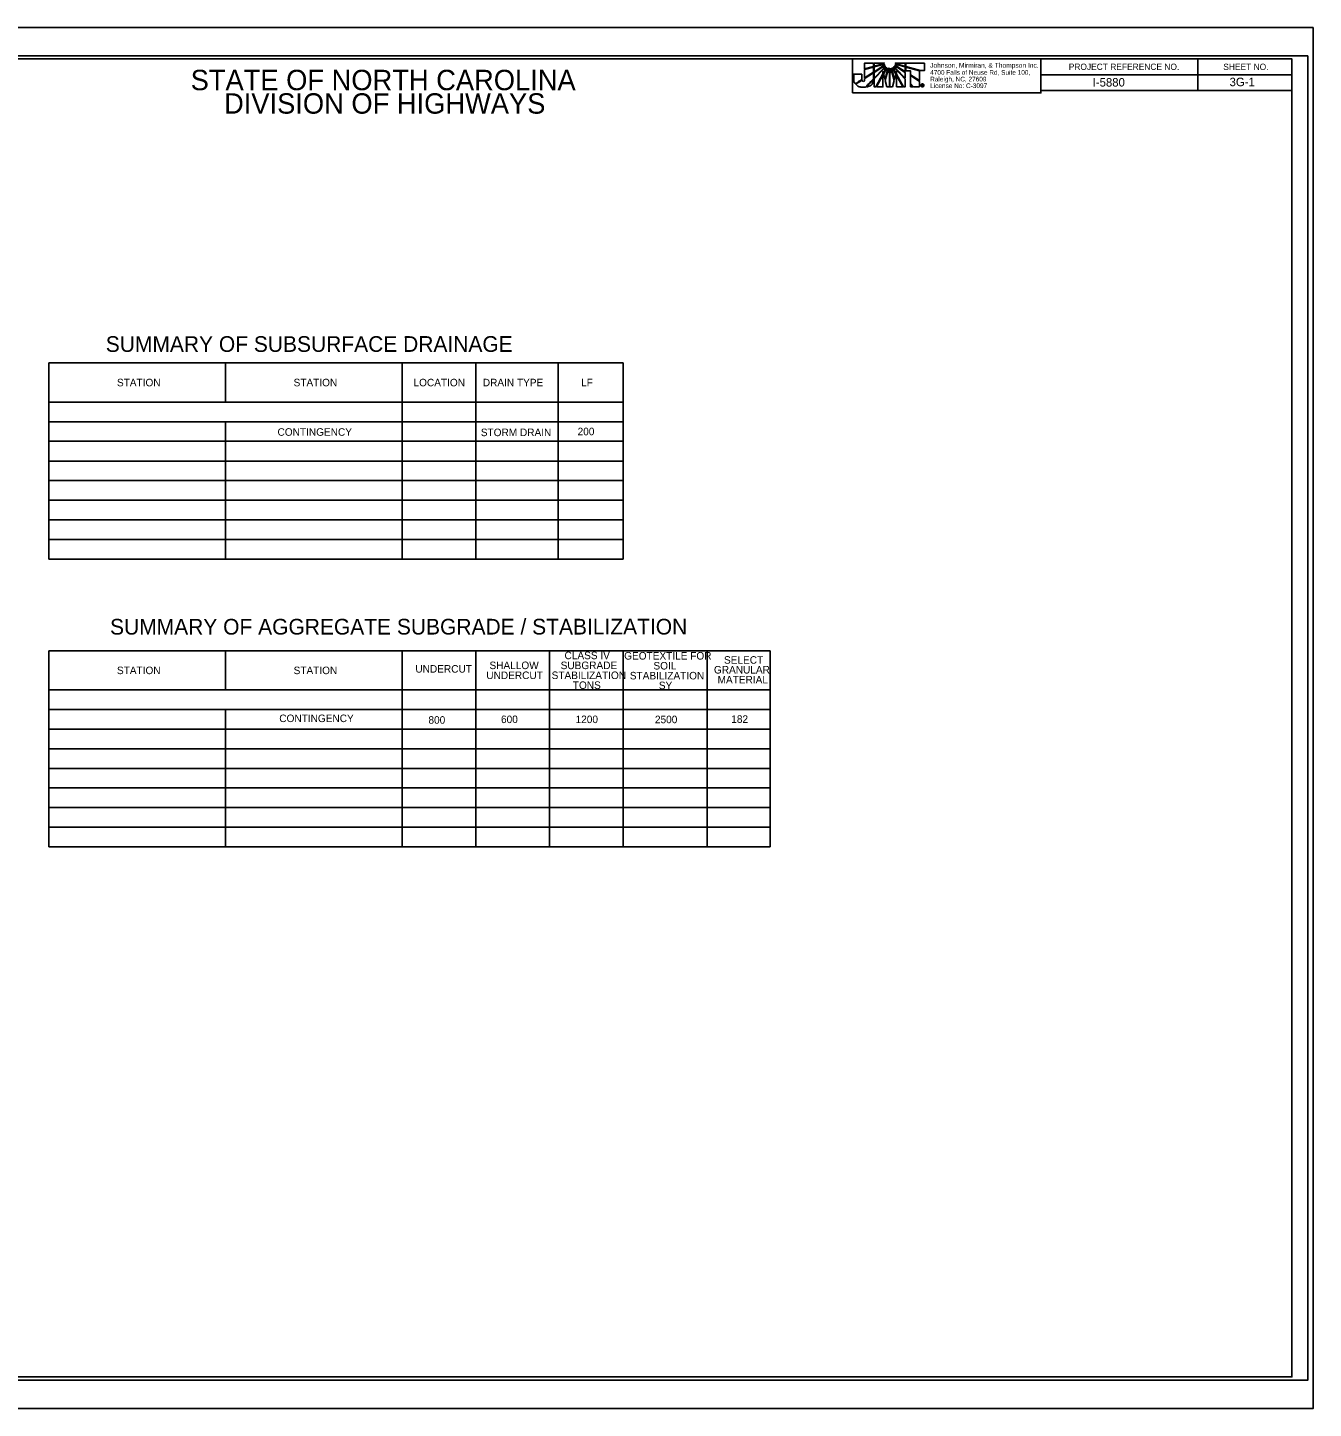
# Model space of a CAD drawing. Extents: x 575597 to 577281, y -53325 to -52225.
# Drawn here: x 576257 to 577281, y -53325 to -52225 of the extents above; entities that cross this region are included whole.
import ezdxf

# ---------------------------------------------------------------- set-up
doc = ezdxf.new("R2010")
doc.units = 0
for name, color, linetype in [('Prop Dimension Text', 7, 'Continuous'), ('Sheet Cutting Line CELL', 7, 'Continuous'), ('Sheet Data Field CELL', 7, 'Continuous'), ('Sheet Plot Border Inside CELL', 7, 'Continuous'), ('Sheet Plot Border Outside CELL', 7, 'Continuous'), ('Sheet Summary Combination CELL', 7, 'Continuous'), ('Sheet Summary Combination Grid CELL', 7, 'Continuous')]:
    doc.layers.add(name, color=color, linetype=linetype)

msp = doc.modelspace()

# ---------------------------------------------------------------- linework, layer by layer
at = {"layer": 'Prop Dimension Text'}
for p, q in [((576930.2, -52253.2), (576923.1, -52253.2)), ((576923.1, -52253.2), (576923.1, -52257.8)), ((576923.1, -52257.8), (576930.2, -52255.9)), ((576930.2, -52256.4), (576923.1, -52258.3)), ((576923.1, -52258.3), (576923.1, -52264.9)), ((576923.1, -52264.9), (576930.2, -52260.4)), ((576930.2, -52255.9), (576930.2, -52253.2)), ((576930.2, -52260.4), (576930.2, -52256.4)), ((576938.8, -52253.1), (576930.9, -52253.1)), ((576930.9, -52253.1), (576930.9, -52255.6)), ((576930.9, -52255.6), (576936.8, -52254)), ((576936.8, -52254.5), (576930.9, -52256.2)), ((576930.9, -52256.2), (576930.9, -52260)), ((576930.9, -52260), (576936.2, -52256.6)), ((576937, -52256.7), (576930.9, -52260.6)), ((576930.9, -52265), (576938.3, -52257.3)), ((576938.6, -52257.6), (576930.9, -52265.7)), ((576930.9, -52260.6), (576930.9, -52265)), ((576936.2, -52256.6), (576939.1, -52254.3)), ((576936.8, -52254), (576938.8, -52253.1)), ((576939.1, -52254.3), (576936.8, -52254.5)), ((576939.6, -52255.4), (576937, -52256.7)), ((576937.8, -52261.7), (576937.8, -52259.9)), ((576937.8, -52259.9), (576938.1, -52261.1)), ((576938.1, -52261.1), (576939.6, -52258.4)), ((576938.3, -52257.3), (576939.6, -52255.4)), ((576940.1, -52258.6), (576938.3, -52261.8)), ((576940.4, -52256.2), (576938.6, -52257.6)), ((576939.5, -52266), (576941.3, -52259)), ((576939.6, -52258.4), (576940.4, -52256.2)), ((576941.7, -52259.4), (576939.7, -52267)), ((576941.5, -52256.8), (576940.1, -52258.6)), ((576941.3, -52259), (576941.5, -52256.8)), ((576942.6, -52257.1), (576941.7, -52259.4)), ((576942.9, -52262.7), (576942.6, -52257.1)), ((576943.8, -52257.1), (576943.4, -52262.7)), ((576944.7, -52259.4), (576943.8, -52257.1)), ((576946.7, -52267.1), (576944.7, -52259.4)), ((576944.9, -52256.8), (576945.1, -52259.1)), ((576946.3, -52258.6), (576944.9, -52256.8)), ((576945.1, -52259.1), (576947, -52266.2)), ((576945.9, -52256.2), (576946.8, -52258.4)), ((576947.8, -52257.6), (576945.9, -52256.2)), ((576948.1, -52261.9), (576946.3, -52258.6)), ((576946.7, -52255.4), (576948.1, -52257.3)), ((576949.4, -52256.7), (576946.7, -52255.4)), ((576946.8, -52258.4), (576948.3, -52261.2)), ((576947.3, -52254.3), (576950.3, -52256.7)), ((576949.5, -52254.5), (576947.3, -52254.3)), ((576955.5, -52253.1), (576947.7, -52253.1)), ((576947.7, -52253.1), (576949.7, -52254)), ((576955.5, -52265.8), (576947.8, -52257.6)), ((576948.1, -52257.3), (576955.5, -52265)), ((576948.3, -52261.2), (576948.6, -52259.8)), ((576948.6, -52259.8), (576948.6, -52261.9)), ((576955.5, -52260.5), (576949.4, -52256.7)), ((576955.5, -52256.2), (576949.5, -52254.5)), ((576949.7, -52254), (576955.5, -52255.7)), ((576950.3, -52256.7), (576955.5, -52259.9)), ((576955.5, -52255.7), (576955.5, -52253.1)), ((576955.5, -52259.9), (576955.5, -52256.2)), ((576955.5, -52265), (576955.5, -52260.5)), ((576970.8, -52253.1), (576956, -52253.1)), ((576956, -52253.1), (576956, -52255.8)), ((576956, -52255.8), (576956, -52255.9)), ((576956, -52255.9), (576967.7, -52259.1)), ((576956, -52256.3), (576956, -52256.3)), ((576956, -52256.3), (576956, -52259.2)), ((576966.9, -52259.4), (576956, -52256.3)), ((576956, -52259.2), (576959.7, -52259.2)), ((576959.7, -52259.2), (576959.7, -52262.5)), ((576966.9, -52267.1), (576966.9, -52259.4)), ((576967.7, -52259.1), (576970.8, -52259.1)), ((576970.8, -52259.1), (576970.8, -52253.1)), ((576930.9, -52265.7), (576930.9, -52272.1)), ((576932.1, -52272.1), (576937.8, -52261.7)), ((576937.8, -52262.7), (576932.6, -52272.1)), ((576937.8, -52272.1), (576937.8, -52262.7)), ((576938.3, -52261.8), (576939.5, -52266)), ((576939.7, -52267), (576941, -52272)), ((576942.9, -52272), (576942.9, -52262.7)), ((576943.4, -52262.7), (576943.4, -52272)), ((576945.4, -52272), (576946.7, -52267.1)), ((576947, -52266.2), (576948.1, -52261.9)), ((576948.6, -52261.9), (576954.2, -52272.1)), ((576953.7, -52272), (576948.6, -52262.9)), ((576948.6, -52262.9), (576948.6, -52272)), ((576955.5, -52272.1), (576955.5, -52265.8)), ((576959.7, -52262.5), (576966.9, -52267.1)), ((576959.7, -52263.1), (576959.7, -52269.4)), ((576966.9, -52267.7), (576959.7, -52263.1)), ((576959.7, -52269.4), (576962.2, -52272)), ((576961.5, -52272), (576959.7, -52270.1)), ((576959.7, -52270.1), (576959.7, -52272)), ((576966.9, -52272), (576966.9, -52267.7)), ((576968.8, -52271.4), (576968.8, -52270.3)), ((576968.8, -52270.3), (576969.2, -52270.3)), ((576969, -52271.4), (576968.8, -52271.4)), ((576969.2, -52270.5), (576969, -52270.5)), ((576969, -52270.5), (576969, -52270.8)), ((576969, -52270.8), (576969.2, -52270.8)), ((576969.2, -52271), (576969, -52271)), ((576969, -52271), (576969, -52271.4)), ((576969.2, -52269.7), (576969.2, -52269.9)), ((576969.2, -52269.9), (576969.2, -52269.7)), ((576969.2, -52270.3), (576969.2, -52270.5)), ((576969.2, -52270.5), (576969.2, -52270.3)), ((576969.2, -52270.3), (576969.3, -52270.3)), ((576969.2, -52270.5), (576969.2, -52270.5)), ((576969.2, -52270.8), (576969.2, -52271)), ((576969.2, -52271), (576969.2, -52270.8)), ((576969.2, -52270.8), (576969.2, -52270.8)), ((576969.2, -52271), (576969.2, -52271)), ((576969.2, -52271.8), (576969.2, -52272)), ((576969.2, -52272), (576969.2, -52271.8)), ((576969.2, -52271.8), (576969.2, -52271.8)), ((576930.9, -52272.1), (576932.1, -52272.1)), ((576932.6, -52272.1), (576937.8, -52272.1)), ((576941, -52272), (576942.9, -52272)), ((576943.4, -52272), (576945.4, -52272)), ((576948.6, -52272), (576953.7, -52272)), ((576954.2, -52272.1), (576955.5, -52272.1)), ((576959.7, -52272), (576961.5, -52272)), ((576962.2, -52272), (576966.9, -52272)), ((576969.2, -52272), (576969.2, -52272))]:
    msp.add_line(p, q, dxfattribs=at)
msp.add_lwpolyline([(576913.6, -52276.9), (577063.6, -52276.9), (577063.6, -52249.8), (576913.6, -52249.8)], close=True, dxfattribs=at)
for points in [[(576923.1, -52257.8), (576930.2, -52255.9), (576930.2, -52253.2), (576923.1, -52253.2), (576923.1, -52257.8)], [(576923.1, -52264.9), (576930.2, -52260.4), (576930.2, -52256.4), (576923.1, -52258.3), (576923.1, -52264.9)], [(576936.8, -52254), (576938.8, -52253.1), (576930.9, -52253.1), (576930.9, -52255.6), (576936.8, -52254)], [(576930.9, -52256.2), (576930.9, -52260), (576936.2, -52256.6), (576939.1, -52254.3), (576936.8, -52254.5), (576930.9, -52256.2)], [(576930.9, -52260.6), (576930.9, -52265), (576938.3, -52257.3), (576939.6, -52255.4), (576937, -52256.7), (576930.9, -52260.6)], [(576940.4, -52256.2), (576938.6, -52257.6), (576930.9, -52265.7), (576930.9, -52272.1), (576932.1, -52272.1), (576937.8, -52261.7), (576937.8, -52259.9), (576938.1, -52261.1), (576939.6, -52258.4), (576940.4, -52256.2)], [(576941.5, -52256.8), (576940.1, -52258.6), (576938.3, -52261.8), (576939.5, -52266), (576941.3, -52259), (576941.5, -52256.8)], [(576941.7, -52259.4), (576939.7, -52267), (576941, -52272), (576942.9, -52272), (576942.9, -52262.7), (576942.6, -52257.1), (576941.7, -52259.4)], [(576943.8, -52257.1), (576943.4, -52262.7), (576943.4, -52272), (576945.4, -52272), (576946.7, -52267.1), (576944.7, -52259.4), (576943.8, -52257.1)], [(576944.9, -52256.8), (576945.1, -52259.1), (576947, -52266.2), (576948.1, -52261.9), (576946.3, -52258.6), (576944.9, -52256.8)], [(576945.9, -52256.2), (576946.8, -52258.4), (576948.3, -52261.2), (576948.6, -52259.8), (576948.6, -52261.9), (576954.2, -52272.1), (576955.5, -52272.1), (576955.5, -52265.8), (576947.8, -52257.6), (576945.9, -52256.2)], [(576946.7, -52255.4), (576948.1, -52257.3), (576955.5, -52265), (576955.5, -52260.5), (576949.4, -52256.7), (576946.7, -52255.4)], [(576947.3, -52254.3), (576950.3, -52256.7), (576955.5, -52259.9), (576955.5, -52256.2), (576949.5, -52254.5), (576947.3, -52254.3)], [(576949.7, -52254), (576955.5, -52255.7), (576955.5, -52253.1), (576947.7, -52253.1), (576949.7, -52254)], [(576970.8, -52253.1), (576956, -52253.1), (576956, -52255.8), (576956, -52255.9), (576967.7, -52259.1), (576970.8, -52259.1), (576970.8, -52253.1)], [(576956, -52256.3), (576956, -52256.3), (576956, -52259.2), (576959.7, -52259.2), (576959.7, -52262.5), (576966.9, -52267.1), (576966.9, -52259.4), (576956, -52256.3)], [(576932.6, -52272.1), (576937.8, -52272.1), (576937.8, -52262.7), (576932.6, -52272.1)], [(576948.6, -52272), (576953.7, -52272), (576948.6, -52262.9), (576948.6, -52272)], [(576959.7, -52263.1), (576959.7, -52269.4), (576962.2, -52272), (576966.9, -52272), (576966.9, -52267.7), (576959.7, -52263.1), (576959.7, -52263.1)], [(576959.7, -52272), (576959.7, -52272), (576961.5, -52272), (576959.7, -52270.1), (576959.7, -52272)], [(576969.7, -52271.1), (576969.7, -52271.2), (576969.7, -52271.2), (576969.7, -52271.3), (576969.7, -52271.4), (576969.5, -52271.4)]]:
    msp.add_lwpolyline(points, dxfattribs=at)
for points, degree in [([(576921.1, -52261.9), (576921.1, -52261.9), (576914.6, -52261.9), (576914.6, -52261.9), (576914.6, -52261.9), (576914.6, -52266), (576914.6, -52266), (576914.6, -52266), (576914.6, -52266.4), (576914.6, -52266.4), (576914.6, -52267.7), (576915.1, -52268.7), (576915.8, -52269.5), (576915.8, -52269.5), (576921.1, -52266.3), (576921.1, -52266.2), (576921.1, -52266.2), (576921.1, -52261.9), (576921.1, -52261.9)], 3), ([(576922.1, -52267.7), (576921.7, -52267.7), (576921.4, -52267.5), (576921.2, -52266.7), (576921.2, -52266.7), (576916.2, -52269.8), (576916.2, -52269.8), (576917.7, -52271.5), (576920.2, -52272.4), (576922.3, -52272.4), (576922.9, -52272.4), (576923.3, -52272.4), (576923.8, -52272.3), (576923.8, -52272.3), (576930.2, -52265.7), (576930.2, -52265.7), (576930.2, -52265.7), (576930.2, -52261), (576930.2, -52261), (576930.2, -52261), (576923.1, -52265.5), (576923.1, -52265.5), (576923.1, -52267.3), (576922.7, -52267.7), (576922.1, -52267.7)], 3), ([(576922.1, -52267.7), (576921.7, -52267.7), (576921.4, -52267.5), (576921.2, -52266.7), (576921.2, -52266.7), (576916.2, -52269.8), (576916.2, -52269.8), (576917.7, -52271.5), (576920.2, -52272.4), (576922.3, -52272.4), (576922.9, -52272.4), (576923.3, -52272.4), (576923.8, -52272.3), (576923.8, -52272.3), (576930.2, -52265.7), (576930.2, -52265.7), (576930.2, -52265.7), (576930.2, -52261), (576930.2, -52261), (576930.2, -52261), (576923.1, -52265.5), (576923.1, -52265.5), (576923.1, -52267.3), (576922.7, -52267.7), (576922.1, -52267.7)], 3), ([(576930.2, -52266.5), (576930.2, -52266.5), (576924.7, -52272.1), (576924.7, -52272.1), (576927.4, -52271.5), (576930, -52269.7), (576930.2, -52266.5)], 3), ([(576969.2, -52272), (576968.9, -52272), (576968.6, -52271.9), (576968.4, -52271.7), (576968.1, -52271.5), (576968, -52271.2), (576968, -52270.8), (576968, -52270.5), (576968.1, -52270.2), (576968.4, -52270), (576968.6, -52269.8), (576968.9, -52269.7), (576969.2, -52269.7)], 3), ([(576969.2, -52269.9), (576969, -52269.9), (576968.7, -52270), (576968.5, -52270.2), (576968.4, -52270.3), (576968.3, -52270.6), (576968.3, -52270.8), (576968.3, -52271.1), (576968.4, -52271.3), (576968.5, -52271.5), (576968.7, -52271.7), (576969, -52271.8), (576969.2, -52271.8)], 3), ([(576969.2, -52269.7), (576969.6, -52269.7), (576969.8, -52269.8), (576970.1, -52270), (576970.3, -52270.2), (576970.4, -52270.5), (576970.4, -52270.8)], 3), ([(576969.2, -52271.8), (576969.5, -52271.8), (576969.7, -52271.7), (576969.9, -52271.5), (576970.1, -52271.3), (576970.2, -52271.1), (576970.2, -52270.8), (576970.2, -52270.6), (576970.1, -52270.3), (576969.9, -52270.2), (576969.7, -52270), (576969.5, -52269.9), (576969.2, -52269.9)], 3), ([(576969.2, -52270.8), (576969.4, -52270.8), (576969.5, -52270.7), (576969.5, -52270.6), (576969.5, -52270.5), (576969.4, -52270.5), (576969.2, -52270.5)], 3), ([(576970.4, -52270.8), (576970.4, -52271.2), (576970.3, -52271.5), (576970.1, -52271.7), (576969.8, -52271.9), (576969.6, -52272), (576969.2, -52272)], 3), ([(576969.4, -52271), (576969.4, -52271), (576969.3, -52271), (576969.2, -52271)], 2), ([(576969.3, -52270.3), (576969.6, -52270.3), (576969.7, -52270.4), (576969.7, -52270.6), (576969.7, -52270.7), (576969.7, -52270.8), (576969.6, -52270.9)], 3), ([(576969.5, -52271.4), (576969.5, -52271.3), (576969.5, -52271.3), (576969.5, -52271.2), (576969.5, -52271.1), (576969.4, -52271), (576969.4, -52271)], 3), ([(576969.6, -52270.9), (576969.6, -52270.9), (576969.7, -52271), (576969.7, -52271.1)], 2)]:
    msp.add_open_spline(points, degree=degree, dxfattribs=at)
at = {"layer": 'Sheet Cutting Line CELL'}
for p, q in [((577280.6, -52224.8), (575596.6, -52224.8)), ((575596.6, -53324.8), (577280.6, -53324.8))]:
    msp.add_line(p, q, dxfattribs=at)
at = {"layer": 'Sheet Plot Border Inside CELL'}
msp.add_lwpolyline([(577276.1, -52247.3), (575609.6, -52247.3), (575609.6, -53302.4), (577276.1, -53302.4)], close=True, dxfattribs=at)
at = {"layer": 'Sheet Plot Border Outside CELL'}
msp.add_lwpolyline([(577280.6, -52224.8), (575596.6, -52224.8), (575596.6, -53324.8), (577280.6, -53324.8)], close=True, dxfattribs=at)
at = {"layer": 'Sheet Summary Combination CELL'}
for p, q in [((577188.6, -52249.9), (577188.6, -52274.9)), ((577063.6, -52262.4), (577263.6, -52262.4)), ((577063.6, -52274.9), (577263.6, -52274.9)), ((576516.2, -52491.9), (576516.2, -52491.9)), ((576497, -52492), (576497, -52492)), ((576504.9, -52492.1), (576504.9, -52492.1)), ((576523.2, -52492), (576523.2, -52492)), ((576497, -52721.3), (576497, -52721.3)), ((576504.9, -52721.4), (576504.9, -52721.4)), ((576516.2, -52721.2), (576516.2, -52721.2)), ((576523.2, -52721.3), (576523.2, -52721.3))]:
    msp.add_line(p, q, dxfattribs=at)
for points in [[(577263.6, -52249.8), (575763.6, -52249.8), (575763.6, -53299.8), (577263.6, -53299.8)], [(577063.6, -52249.8), (577263.6, -52249.8), (577263.6, -52274.9), (577063.6, -52274.9)]]:
    msp.add_lwpolyline(points, close=True, dxfattribs=at)
at = {"layer": 'Sheet Summary Combination Grid CELL'}
for p, q in [((576273.4, -52491.9), (576730.8, -52491.9)), ((576273.4, -52491.9), (576273.4, -52648.2)), ((576414.2, -52491.9), (576414.2, -52523.2)), ((576554.9, -52491.9), (576554.9, -52648.2)), ((576613.5, -52491.9), (576613.5, -52648.2)), ((576679.1, -52491.3), (576679.1, -52647.6)), ((576730.8, -52491.9), (576730.8, -52648.2)), ((576273.4, -52523.2), (576730.8, -52523.2)), ((576273.4, -52538.8), (576730.8, -52538.8)), ((576414.2, -52538.8), (576414.2, -52648.2)), ((576273.4, -52554.4), (576730.8, -52554.4)), ((576273.4, -52570.1), (576730.8, -52570.1)), ((576273.4, -52585.7), (576730.8, -52585.7)), ((576273.4, -52601.3), (576730.8, -52601.3)), ((576273.4, -52616.9), (576730.8, -52616.9)), ((576273.4, -52632.6), (576730.8, -52632.6)), ((576273.4, -52648.2), (576730.8, -52648.2)), ((576273.4, -52648.2), (576730.8, -52648.2)), ((576273.4, -52721.2), (576848, -52721.2)), ((576273.4, -52721.2), (576273.4, -52877.5)), ((576414.2, -52721.2), (576414.2, -52752.5)), ((576554.9, -52721.2), (576554.9, -52877.5)), ((576613.5, -52721.2), (576613.5, -52877.5)), ((576672.2, -52721.2), (576672.2, -52877.5)), ((576730.8, -52721.2), (576730.8, -52877.5)), ((576797.8, -52721.2), (576797.8, -52877.5)), ((576848, -52721.2), (576848, -52877.5)), ((576273.4, -52752.5), (576848, -52752.5)), ((576273.4, -52768.1), (576848, -52768.1)), ((576414.2, -52768.1), (576414.2, -52877.5)), ((576273.4, -52783.7), (576848, -52783.7)), ((576273.4, -52799.4), (576848, -52799.4)), ((576273.4, -52815), (576848, -52815)), ((576273.4, -52830.6), (576848, -52830.6)), ((576273.4, -52846.2), (576848, -52846.2)), ((576273.4, -52861.9), (576848, -52861.9)), ((576273.4, -52877.5), (576848, -52877.5))]:
    msp.add_line(p, q, dxfattribs=at)

# ---------------------------------------------------------------- texts
at = {"layer": 'Prop Dimension Text'}
for s, height, p in [('Johnson, Mirmiran, & Thompson Inc.', 3.831, (576975.4, -52256.8)), ('4700 Falls of Neuse Rd, Suite 100, ', 3.722, (576975.4, -52262.4)), ('Raleigh, NC, 27609', 3.722, (576975.4, -52267.7)), ('License No: C-3097', 3.722, (576975.4, -52273))]:
    msp.add_text(s, height=height, rotation=360, dxfattribs=at).set_placement(p)
at = {"layer": 'Sheet Data Field CELL'}
for s, p in [('I-5880', (577104.9, -52271.8)), ('3G-1', (577213.9, -52271.5))]:
    msp.add_text(s, height=6.75, dxfattribs=at).set_placement(p)
at = {"layer": 'Sheet Summary Combination CELL'}
for s, height, p in [('STATE OF NORTH CAROLINA', 16.25, (576386.4, -52274.7)), ('PROJECT REFERENCE NO.', 5, (577085.8, -52258.5)), ('SHEET NO.', 5, (577208.9, -52258.6)), ('DIVISION OF HIGHWAYS', 16.25, (576413, -52293.4)), ('STATION', 6, (576327.7, -52510.6)), ('STATION', 6, (576468.4, -52510.6)), ('LOCATION', 6, (576563.9, -52510.6)), ('DRAIN TYPE', 6, (576619.1, -52510.6)), ('LF', 6, (576697.4, -52510.6)), ('CONTINGENCY', 6, (576455.6, -52550)), ('STORM DRAIN', 6, (576617.5, -52550.3)), ('200', 6, (576694.6, -52549.6)), ('CLASS IV', 6, (576684.2, -52728)), ('GEOTEXTILE FOR', 6, (576731.7, -52728.3)), ('STATION', 6, (576327.7, -52739.9)), ('STATION', 6, (576468.4, -52739.9)), ('UNDERCUT', 6, (576565.4, -52738.7)), ('SHALLOW', 6, (576624.4, -52735.9)), ('SUBGRADE', 6, (576681.1, -52735.9)), ('SOIL', 6, (576755, -52736.2)), ('GRANULAR', 6, (576803.2, -52739.4)), ('SELECT', 6, (576811.2, -52731.6)), ('UNDERCUT', 6, (576621.9, -52743.8)), ('STABILIZATION', 6, (576673.9, -52743.8)), ('STABILIZATION', 6, (576736.2, -52744.1)), ('MATERIAL', 6, (576806.1, -52747.3)), ('TONS', 6, (576690.8, -52751.7)), ('SY', 6, (576759.3, -52751.9)), ('CONTINGENCY', 6, (576457, -52778.1)), ('800', 6, (576575.8, -52779.4)), ('600', 6, (576633.6, -52778.9)), ('1200', 6, (576693, -52778.9)), ('2500', 6, (576756.2, -52779)), ('182', 6, (576817, -52778.7))]:
    msp.add_text(s, height=height, dxfattribs=at).set_placement(p)
for s, p in [('SUMMARY OF SUBSURFACE DRAINAGE', (576318.8, -52483.2)), ('SUMMARY OF AGGREGATE SUBGRADE / STABILIZATION', (576322.2, -52708.4))]:
    msp.add_text(s, height=12.5, rotation=0.0119, dxfattribs=at).set_placement(p)

doc.saveas('drawing.dxf')
